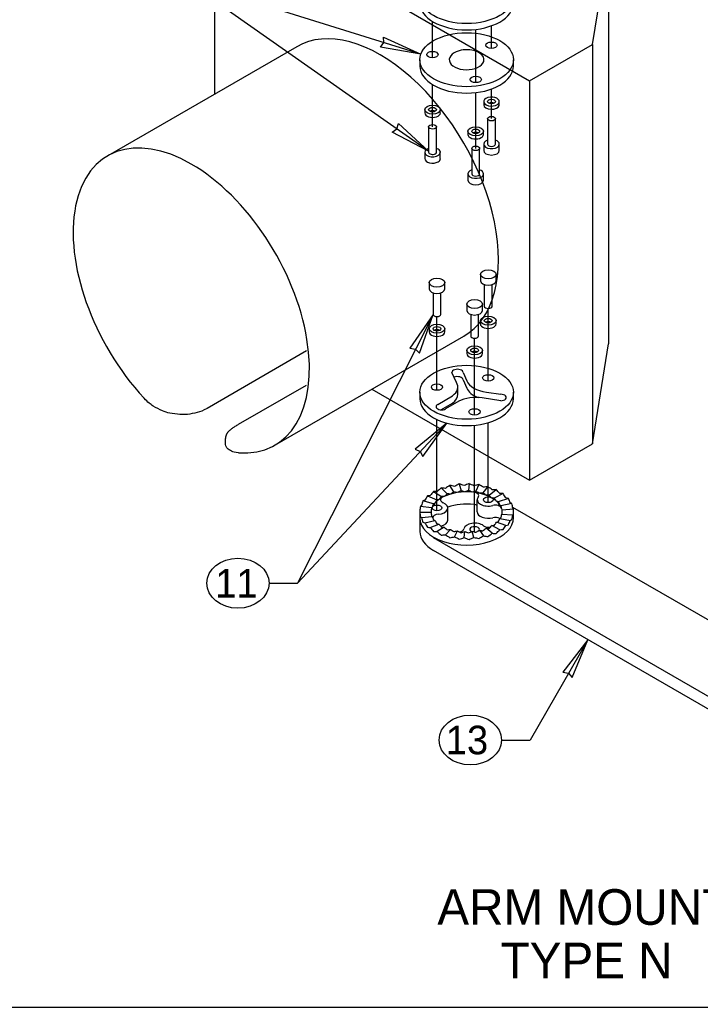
# Model space of a CAD drawing. Extents: x 99862 to 104211, y 98939 to 105076.
# Drawn here: x 100738 to 101120, y 100000 to 100554 of the extents above; entities that cross this region are included whole.
import ezdxf

# ---------------------------------------------------------------- set-up
doc = ezdxf.new("R2010")
doc.units = 0
for name, color, linetype in [('Level 1', 7, 'Continuous'), ('Level 11', 7, 'Continuous'), ('Level 13', 7, 'Continuous'), ('Level 15', 7, 'Continuous'), ('Level 20', 7, 'Continuous'), ('Level 26', 7, 'Continuous')]:
    doc.layers.add(name, color=color, linetype=linetype)

msp = doc.modelspace()

# ---------------------------------------------------------------- linework, layer by layer
at = {"layer": 'Level 1'}
msp.add_lwpolyline([(99862, 99999.5), (103151, 99999.5), (103151, 102075.5), (99862, 102075.5)], close=True, dxfattribs=at)
at = {"layer": 'Level 11'}
for p, q in [((100962.21, 100531.18), (100962.21, 100527.6)), ((101014.71, 100527.6), (101014.71, 100531.18)), ((100998.04, 100507.7), (100998.04, 100505.91)), ((101006.79, 100505.91), (101006.79, 100507.7)), ((100964.95, 100503.14), (100964.95, 100501.35)), ((100973.7, 100501.35), (100973.7, 100503.14)), ((101000.22, 100498.12), (101000.22, 100483.83)), ((101004.6, 100483.83), (101004.6, 100498.12)), ((100967.14, 100493.55), (100967.14, 100479.27)), ((100971.51, 100479.27), (100971.51, 100493.55)), ((100989.2, 100491.02), (100989.2, 100489.24)), ((100997.95, 100489.24), (100997.95, 100491.02)), ((100998.04, 100483.83), (100998.04, 100480.25)), ((101006.79, 100480.25), (101006.79, 100483.83)), ((100964.95, 100479.27), (100964.95, 100475.69)), ((100973.7, 100475.69), (100973.7, 100479.27)), ((100991.39, 100481.44), (100991.39, 100467.15)), ((100995.76, 100467.15), (100995.76, 100481.44)), ((100989.2, 100467.15), (100989.2, 100463.58)), ((100997.95, 100463.58), (100997.95, 100467.15)), ((100996.19, 100410.72), (100996.19, 100407.15)), ((101004.94, 100407.15), (101004.94, 100410.72)), ((100967.42, 100406.16), (100967.42, 100402.59)), ((100976.17, 100402.59), (100976.17, 100406.16)), ((100998.38, 100404.96), (100998.38, 100392.86)), ((101002.75, 100392.86), (101002.75, 100404.96)), ((100969.61, 100400.4), (100969.61, 100388.3)), ((100973.99, 100388.3), (100973.99, 100400.4)), ((100988.54, 100394.05), (100988.54, 100390.47)), ((100997.29, 100390.47), (100997.29, 100394.05)), ((100990.73, 100388.29), (100990.73, 100376.19)), ((100995.1, 100376.19), (100995.1, 100388.29)), ((100996.19, 100384.77), (100996.19, 100382.98)), ((101004.94, 100382.98), (101004.94, 100384.77)), ((100967.42, 100380.21), (100967.42, 100378.42)), ((100976.17, 100378.42), (100976.17, 100380.21)), ((100988.54, 100368.09), (100988.54, 100366.31)), ((100997.29, 100366.31), (100997.29, 100368.09)), ((100982.75, 100350.13), (100980.19, 100355.65)), ((100986.48, 100355.65), (100988.62, 100351.04)), ((100986.48, 100351.54), (100988.62, 100346.93)), ((100983.47, 100343.46), (100983.47, 100347.57)), ((100962.21, 100344.61), (100962.21, 100341.03)), ((100972.23, 100337.81), (100980.59, 100342.63)), ((101007.59, 100339.83), (100997.21, 100341.38)), ((100999.61, 100344.7), (101007.59, 100343.46)), ((101014.71, 100341.03), (101014.71, 100344.61)), ((100974.01, 100334.72), (100980.59, 100338.52)), ((100984.08, 100339.51), (100976.68, 100335.24))]:
    msp.add_line(p, q, dxfattribs=at)
for centre, major_axis in [((100988.46, 100566.64), (26.25, 0)), ((100988.46, 100531.18), (26.25, 0)), ((101002.38, 100539.31), (3.14, 0)), ((100969.3, 100534.06), (3.14, 0)), ((100993.58, 100520.13), (3.14, 0)), ((101002.41, 100507.7), (2.19, 0)), ((100969.33, 100503.14), (-4.38, 0)), ((100969.33, 100503.14), (2.19, 0)), ((101002.41, 100498.12), (2.19, 0)), ((100969.33, 100493.55), (2.19, 0)), ((100993.57, 100491.02), (-4.38, 0)), ((100993.57, 100491.02), (2.19, 0)), ((100993.57, 100481.44), (2.19, 0)), ((101000.56, 100410.72), (4.38, 0)), ((100971.8, 100406.16), (4.38, 0)), ((100992.92, 100394.05), (4.38, 0)), ((101000.56, 100384.77), (-4.38, 0)), ((101000.56, 100384.77), (2.19, 0)), ((100971.8, 100380.21), (-4.38, 0)), ((100971.8, 100380.21), (2.19, 0)), ((100992.92, 100368.09), (-4.38, 0)), ((100992.92, 100368.09), (2.19, 0)), ((100988.46, 100344.61), (26.25, 0)), ((101000.56, 100352.64), (3.14, 0)), ((100971.8, 100347.5), (3.14, 0)), ((100992.92, 100333.56), (3.14, 0))]:
    msp.add_ellipse(centre, major_axis=major_axis, ratio=0.57735, dxfattribs=at)
for centre, major_axis, start_param, end_param in [((100988.46, 100563.07), (26.25, 0), 3.141593, 6.283185), ((100988.46, 100531.18), (9.74, 0), 2.024427, 6.283185), ((100988.46, 100531.18), (9.74, 0), 0, 2.024427), ((100988.46, 100527.6), (26.25, 0), 3.141593, 6.283185), ((101002.41, 100507.7), (-4.38, 0), 4.851782, 8.738551), ((101002.41, 100505.91), (-4.38, 0), 6.283185, 9.281643), ((101002.41, 100505.91), (2.19, 0), 0.785398, 2.356194), ((101002.41, 100507.7), (-4.38, 0), 2.455366, 4.851782), ((101002.41, 100505.91), (-4.38, 0), 2.998458, 3.141593), ((100969.33, 100501.35), (-4.38, 0), 6.283185, 9.424778), ((100969.33, 100501.35), (2.19, 0), 0.785398, 2.356194), ((100993.57, 100489.24), (2.19, 0), 0.785398, 2.356194), ((100993.57, 100489.24), (-4.38, 0), 0, 3.141593), ((101002.41, 100483.83), (4.38, 0), 2.094395, 6.283185), ((101002.41, 100483.83), (2.19, 0), 3.141593, 6.283185), ((101002.41, 100483.83), (4.38, 0), 6.283185, 7.330383), ((100969.33, 100479.27), (4.38, 0), 2.094395, 6.283185), ((100969.33, 100479.27), (2.19, 0), 3.141593, 5.497787), ((100969.33, 100479.27), (2.19, 0), 5.497787, 6.283185), ((100969.33, 100479.27), (4.38, 0), 0, 1.047198), ((101002.41, 100480.25), (4.38, 0), 3.141593, 6.283185), ((100969.33, 100475.69), (4.38, 0), 3.141593, 5.497787), ((100969.33, 100475.69), (4.38, 0), 5.497787, 6.283185), ((100993.57, 100467.15), (4.38, 0), 2.094395, 6.283185), ((100993.57, 100467.15), (2.19, 0), 3.141593, 6.283185), ((100993.57, 100467.15), (4.38, 0), 0, 1.047198), ((100993.57, 100463.58), (4.38, 0), 3.141593, 6.283185), ((101000.56, 100407.15), (4.38, 0), 3.141593, 6.283185), ((100971.8, 100402.59), (4.38, 0), 3.141593, 6.283185), ((100992.92, 100390.47), (4.38, 0), 3.141593, 6.283185), ((101000.56, 100392.86), (2.19, 0), 3.141593, 6.283185), ((100971.8, 100388.3), (2.19, 0), 3.141593, 6.283185), ((101000.56, 100382.98), (2.19, 0), 0.785398, 2.356194), ((100971.8, 100378.42), (2.19, 0), 0.785398, 2.356194), ((101000.56, 100382.98), (-4.38, 0), 6.283185, 9.424778), ((100971.8, 100378.42), (-4.38, 0), 6.283185, 9.424778), ((100992.92, 100376.19), (2.19, 0), 3.141593, 6.283185), ((100992.92, 100366.31), (2.19, 0), 0.785398, 2.356194), ((100992.92, 100366.31), (-4.38, 0), 6.283185, 9.424778), ((100983.34, 100355.65), (3.14, 0), 0, 3.141593), ((100983.34, 100351.54), (3.14, 0), 0, 2.2227), ((101002.46, 100352.69), (14.14, 0), 3.345037, 4.508944), ((100969.33, 100347.57), (14.14, 0), 5.634137, 6.603339), ((101002.46, 100348.58), (14.14, 0), 3.345037, 4.166798), ((100988.46, 100341.03), (26.25, 0), 3.141593, 6.283185), ((100969.33, 100343.46), (14.14, 0), 5.634137, 6.283185), ((100993.59, 100333.56), (14.02, 0), 1.308997, 2.31608), ((101007.59, 100341.65), (3.14, 0), 4.712389, 7.853982), ((100974.46, 100336.52), (3.14, 0), 2.356194, 5.497787)]:
    msp.add_ellipse(centre, major_axis=major_axis, ratio=0.57735, start_param=start_param, end_param=end_param, dxfattribs=at)
at = {"layer": 'Level 13'}
for p, q in [((100974.16, 100290.87), (100977.59, 100287.57)), ((100981.31, 100288.66), (100979.05, 100292.31)), ((100984.35, 100293.13), (100985.34, 100289.29)), ((100989.84, 100293.3), (100989.51, 100289.41)), ((100995.26, 100292.8), (100993.63, 100289.04)), ((101000.38, 100291.66), (100997.52, 100288.17)), ((101001.01, 100286.86), (101004.98, 100289.94)), ((100966.44, 100286.41), (100971.72, 100284.18)), ((100969.89, 100288.88), (100974.35, 100286.06)), ((100994.42, 100277.41), (100994.42, 100284.27)), ((101008.87, 100287.69), (101003.97, 100285.15)), ((101011.86, 100285.04), (101006.24, 100283.14)), ((100968.75, 100279.71), (100962.52, 100280.53)), ((100969.83, 100282.04), (100963.94, 100283.59)), ((100977.91, 100272.79), (100977.91, 100279.65)), ((101013.83, 100282.08), (101007.74, 100280.89)), ((101014.69, 100278.95), (101008.39, 100278.51)), ((101014.28, 100280.15), (101150.39, 100201.57)), ((100962.2, 100277.64), (100962.21, 100274.01)), ((100962.21, 100274.01), (100962.21, 100266.48)), ((100962.24, 100277.36), (100968.53, 100277.31)), ((100963.09, 100274.23), (100969.19, 100274.93)), ((101007.09, 100273.78), (101012.98, 100272.72)), ((101008.17, 100276.11), (101014.4, 100275.78)), ((101014.71, 100274.23), (101014.72, 100277.64)), ((100965.06, 100271.27), (100970.68, 100272.68)), ((100968.05, 100268.61), (100972.95, 100270.66)), ((100975.91, 100268.95), (100971.94, 100266.37)), ((100976.54, 100264.65), (100979.4, 100267.64)), ((101002.76, 100265.44), (100999.33, 100268.25)), ((101007.03, 100267.43), (101002.57, 100269.76)), ((101010.48, 100269.9), (101005.2, 100271.63)), ((101143.14, 100162.89), (100969.9, 100262.91)), ((100981.66, 100263.51), (100983.3, 100266.78)), ((100987.09, 100263.01), (100987.42, 100266.4)), ((100992.57, 100263.18), (100991.58, 100266.53)), ((100995.61, 100267.15), (100997.87, 100264)), ((101143.14, 100155.74), (100969.9, 100255.76))]:
    msp.add_line(p, q, dxfattribs=at)
for centre, major_axis, ratio, start_param, end_param in [((100988.46, 100277.13), (23.98, 15.69), 0.682966, 1.726553, 1.831273), ((100988.46, 100277.13), (-26, 10.17), 0.360362, 5.323611, 5.42833), ((100988.46, 100277.13), (24.51, 15.22), 0.6191, 1.570348, 1.675068), ((100988.46, 100277.13), (-25.82, 11.65), 0.413044, 5.158439, 5.263158), ((100988.46, 100277.13), (24.99, 14.48), 0.557438, 1.415448, 1.520168), ((100988.46, 100277.13), (-25.55, 12.94), 0.468967, 4.997892, 5.102611), ((100988.46, 100277.13), (25.39, 13.51), 0.497899, 1.259485, 1.364205), ((100988.46, 100277.13), (-25.2, 14.02), 0.527399, 4.840753, 4.945473), ((100988.46, 100277.13), (25.69, 12.32), 0.440657, 1.100807, 1.205527), ((100988.46, 100277.13), (-24.76, 14.88), 0.588004, 4.685558, 4.790278), ((100988.46, 100277.13), (25.92, 10.93), 0.386234, 0.938087, 1.042807), ((100988.46, 100277.13), (-24.25, 15.49), 0.650745, 4.530376, 4.635096), ((100988.46, 100277.13), (26.07, 9.36), 0.335596, 0.770561, 0.874936), ((100988.46, 100277.13), (-23.74, 15.68), 0.716006, 4.368664, 4.47373), ((100988.46, 100277.13), (23.05, 15.38), 0.818147, 2.06586, 2.17058), ((100988.46, 100277.13), (-26.2, 6.69), 0.270119, 5.671382, 5.776101), ((100988.46, 100277.13), (23.44, 15.81), 0.749264, 1.888318, 1.993037), ((100988.46, 100277.2), (19.96, 0), 0.57735, 2.313319, 2.894414), ((100988.46, 100277.13), (-26.13, 8.51), 0.312139, 5.494389, 5.599109), ((100988.46, 100277.13), (19.91, -5.08), 0.270119, 2.538903, 2.634509), ((100988.46, 100277.13), (-17.81, -12.01), 0.749264, 5.02991, 5.125516), ((100977.33, 100284.2), (3.5, 0), 0.57735, 2.313319, 4.097386), ((100988.46, 100277.13), (19.85, -6.47), 0.312139, 2.36191, 2.457516), ((100988.46, 100277.2), (19.96, 0), 0.57735, 1.374635, 2.313319), ((100988.46, 100277.13), (-18.22, -11.92), 0.682966, 4.868145, 4.963751), ((100988.46, 100277.13), (19.76, -7.73), 0.360362, 2.191132, 2.286738), ((100988.46, 100277.13), (-18.63, -11.56), 0.6191, 4.711941, 4.807546), ((100988.46, 100277.13), (19.62, -8.85), 0.413044, 2.02596, 2.121566), ((100988.46, 100277.13), (-18.99, -11), 0.557438, 4.557041, 4.652646), ((100988.46, 100277.13), (19.42, -9.83), 0.468967, 1.865413, 1.961019), ((100988.46, 100277.13), (-19.29, -10.26), 0.497899, 4.401077, 4.496683), ((100988.46, 100277.13), (19.15, -10.65), 0.527399, 1.708274, 1.80388), ((100988.46, 100277.13), (-19.52, -9.36), 0.440657, 4.2424, 4.338005), ((100988.46, 100277.2), (19.96, 0), 0.57735, 0.157092, 1.372405), ((100991.74, 100286.51), (3.5, 0), 0.57735, 5.869558, 7.653625), ((100988.46, 100277.13), (18.81, -11.31), 0.588004, 1.55308, 1.648685), ((101000.56, 100284.27), (6.14, 0), 0.57735, 2.727965, 5.138297), ((100988.46, 100277.13), (-19.7, -8.31), 0.386234, 4.07968, 4.175285), ((100988.46, 100277.13), (18.43, -11.77), 0.650745, 1.397898, 1.493503), ((100988.46, 100277.13), (-19.81, -7.11), 0.335596, 3.912154, 4.007414), ((100988.46, 100277.13), (18.04, -11.91), 0.716006, 1.236246, 1.332137), ((100988.46, 100277.13), (-19.88, -5.76), 0.292084, 3.737537, 3.833428), ((100988.46, 100277.13), (17.64, -11.92), 0.783391, 1.072023, 1.167282), ((100988.46, 100277.13), (26.17, 7.58), 0.292084, 0.595944, 0.70101), ((100988.46, 100277.13), (-23.21, 15.69), 0.783391, 4.204501, 4.308875), ((100988.46, 100277.13), (26.22, 5.73), 0.252109, 0.416228, 0.520948), ((100988.46, 100277.13), (-23.03, 14.79), 0.853385, 4.009326, 4.114045), ((100988.46, 100277.13), (25.81, 5.13), 0.947565, 2.798423, 2.903143), ((100988.46, 100277.13), (-26.25, 2.67), 0.213589, 6.04308, 6.1478), ((100988.46, 100277.13), (23.3, 13.64), 0.888613, 2.295514, 2.400234), ((100988.46, 100277.13), (-26.24, 4.73), 0.236491, 5.854579, 5.959298), ((100988.46, 100277.13), (-19.61, -3.9), 0.947565, 5.940016, 6.044735), ((100988.46, 100277.2), (19.96, 0), 0.57735, 2.888908, 3.080118), ((100988.46, 100277.13), (19.95, -2.03), 0.213589, 2.910602, 3.006207), ((100988.46, 100277.13), (-17.7, -10.36), 0.888613, 5.437107, 5.532712), ((100988.46, 100277.13), (19.94, -3.6), 0.236491, 2.7221, 2.817706), ((100988.46, 100277.13), (-17.51, -11.69), 0.818147, 5.207453, 5.303058), ((100971.77, 100279.65), (6.14, 0), 0.57735, 4.828647, 7.238979), ((100988.46, 100270.34), (-19.96, 0), 0.57735, 4.512032, 5.272259), ((100991.74, 100279.65), (-3.5, 0), 0.57735, 3.837098, 4.512032), ((101004.55, 100279.2), (3.5, 0), 0.57735, 0.212638, 1.996705), ((100988.46, 100277.13), (-19.92, -4.35), 0.252109, 3.557821, 3.653426), ((100988.46, 100277.13), (17.5, -11.24), 0.853385, 0.876847, 0.972453), ((100988.46, 100277.13), (-19.95, -2.82), 0.223561, 3.371796, 3.467401), ((100988.46, 100277.13), (18.35, -8.49), 0.922162, 0.569546, 0.665151), ((100988.46, 100277.2), (19.96, 0), 0.57735, 0.147965, 0.166194), ((100988.46, 100277.13), (-19.95, -1.22), 0.206802, 3.181297, 3.276903), ((100988.46, 100277.13), (26.25, 3.71), 0.223561, 0.230203, 0.334923), ((100988.46, 100277.13), (-24.15, 11.18), 0.922162, 3.702024, 3.806744), ((100988.46, 100277.13), (26.26, 1.61), 0.206802, 0.039705, 0.144424), ((100988.46, 100277.13), (25.81, 5.13), 0.947565, 6.044735, 6.149455), ((100988.46, 100277.13), (-26.26, 0.54), 0.203365, 6.234982, 6.339702), ((100988.46, 100274.01), (-26.25, 0), 0.57735, 6.283185, 9.439299), ((100988.46, 100277.13), (-24.15, 11.18), 0.922162, 0.455712, 0.560431), ((100988.46, 100277.13), (26.26, 1.61), 0.206802, 3.286017, 3.390737), ((100988.46, 100277.13), (-23.03, 14.79), 0.853385, 0.763013, 0.867733), ((100988.46, 100277.13), (19.95, -0.41), 0.203365, 3.09339, 3.19811), ((100988.46, 100277.13), (18.35, -8.49), 0.922162, 3.597304, 3.702024), ((100988.46, 100277.13), (-19.95, -1.22), 0.206802, 0.144424, 0.249144), ((100988.46, 100277.13), (17.5, -11.24), 0.853385, 3.904606, 4.009326), ((100972.89, 100274.12), (3.5, 0), 0.57735, 1.687054, 3.090654), ((101000.56, 100277.41), (-6.14, 0), 0.57735, 0, 1.996705), ((101004.55, 100272.34), (-3.5, 0), 0.57735, 3.904893, 5.138297), ((100988.46, 100277.13), (-17.51, -11.69), 0.818147, 2.17058, 2.2753), ((100988.46, 100277.13), (19.95, -2.03), 0.213589, 5.93836, 6.04308), ((100988.46, 100277.13), (-17.7, -10.36), 0.888613, 2.400234, 2.504954), ((100988.46, 100277.13), (19.95, -0.41), 0.203365, 6.130263, 6.32127), ((100988.46, 100277.13), (-19.61, -3.9), 0.947565, 2.921575, 3.007863), ((100988.46, 100277.13), (-26.25, 2.67), 0.213589, 2.796768, 2.901488), ((100988.46, 100277.13), (23.3, 13.64), 0.888613, 5.541827, 5.646547), ((100988.46, 100277.13), (-26.26, 0.54), 0.203365, 2.98867, 3.09339), ((100988.46, 100277.13), (26.25, 3.71), 0.223561, 3.476515, 3.581235), ((100988.46, 100277.13), (-23.21, 15.69), 0.783391, 0.958188, 1.062908), ((100988.46, 100277.13), (26.22, 5.73), 0.252109, 3.662541, 3.766915), ((100988.46, 100277.13), (-23.74, 15.68), 0.716006, 1.122007, 1.227072), ((100988.46, 100277.13), (-19.95, -2.82), 0.223561, 0.334923, 0.439643), ((100988.46, 100277.13), (17.64, -11.92), 0.783391, 4.099781, 4.204501), ((100988.46, 100277.13), (-19.92, -4.35), 0.252109, 0.520948, 0.625322), ((100988.46, 100277.13), (18.04, -11.91), 0.716006, 4.263599, 4.368664), ((100971.77, 100272.79), (6.14, 0), 0.57735, 5.069342, 6.283185), ((100988.46, 100277.13), (-19.88, -5.76), 0.292084, 0.70101, 0.806075), ((100988.46, 100277.13), (18.43, -11.77), 0.650745, 4.426002, 4.530376), ((100988.46, 100277.13), (-19.81, -7.11), 0.335596, 0.874936, 0.979655), ((100988.46, 100277.13), (18.81, -11.31), 0.588004, 4.580838, 4.685558), ((100983.42, 100268.15), (3.5, 0), 0.57735, 4.992525, 6.185337), ((100993.02, 100267.61), (6.14, 0), 0.57735, 0.633413, 3.043745), ((100992.92, 100267.59), (2.73, 0), 0.57735, 5.958058, 10.322476), ((100988.46, 100277.13), (-18.63, -11.56), 0.6191, 1.675068, 1.779788), ((101000.79, 100270.9), (3.5, 0), 0.57735, 3.775005, 5.014613), ((100988.46, 100277.13), (19.85, -6.47), 0.312139, 5.389669, 5.494389), ((100988.46, 100277.13), (-18.22, -11.92), 0.682966, 1.831273, 1.935992), ((100988.46, 100277.13), (19.91, -5.08), 0.270119, 5.566662, 5.671382), ((100988.46, 100277.13), (-17.81, -12.01), 0.749264, 1.993037, 2.097757), ((100988.46, 100277.13), (19.94, -3.6), 0.236491, 5.749859, 5.854579), ((100988.46, 100277.13), (23.44, 15.81), 0.749264, 5.13463, 5.23935), ((100988.46, 100277.13), (-26.24, 4.73), 0.236491, 2.608266, 2.712986), ((100988.46, 100277.13), (23.05, 15.38), 0.818147, 5.312172, 5.416892), ((100988.46, 100266.48), (26.25, 0), 0.57735, 3.141593, 3.926991), ((100988.46, 100277.13), (26.17, 7.58), 0.292084, 3.842602, 3.947667), ((100988.46, 100277.13), (-24.25, 15.49), 0.650745, 1.284409, 1.388784), ((100988.46, 100277.13), (26.07, 9.36), 0.335596, 4.016528, 4.121248), ((100988.46, 100277.13), (-24.76, 14.88), 0.588004, 1.439246, 1.543965), ((100988.46, 100277.13), (25.92, 10.93), 0.386234, 4.184399, 4.289119), ((100988.46, 100277.13), (-19.7, -8.31), 0.386234, 1.042807, 1.147526), ((100988.46, 100277.13), (-25.2, 14.02), 0.527399, 1.59444, 1.69916), ((100988.46, 100277.13), (19.15, -10.65), 0.527399, 4.736033, 4.840753), ((100988.46, 100277.13), (25.69, 12.32), 0.440657, 4.34712, 4.45184), ((100988.46, 100277.13), (-19.52, -9.36), 0.440657, 1.205527, 1.310247), ((100988.46, 100277.13), (-25.55, 12.94), 0.468967, 1.751579, 1.856299), ((100988.46, 100277.13), (19.42, -9.83), 0.468967, 4.893172, 4.997892), ((100988.46, 100277.13), (-19.29, -10.26), 0.497899, 1.364205, 1.468924), ((100988.46, 100277.13), (25.39, 13.51), 0.497899, 4.505797, 4.610517), ((100988.46, 100277.13), (19.62, -8.85), 0.413044, 5.053719, 5.158439), ((100988.46, 100277.13), (-25.82, 11.65), 0.413044, 1.912126, 2.016846), ((100988.46, 100277.13), (-18.99, -11), 0.557438, 1.520168, 1.624888), ((100988.46, 100277.13), (24.99, 14.48), 0.557438, 4.66176, 4.76648), ((100988.46, 100277.13), (19.76, -7.73), 0.360362, 5.218891, 5.323611), ((100988.46, 100277.13), (-26, 10.17), 0.360362, 2.077298, 2.182018), ((100988.46, 100277.13), (24.51, 15.22), 0.6191, 4.81666, 4.92138), ((100988.46, 100277.13), (-26.13, 8.51), 0.312139, 2.248076, 2.352796), ((100988.46, 100277.13), (23.98, 15.69), 0.682966, 4.972865, 5.077585), ((100988.46, 100277.13), (-26.2, 6.69), 0.270119, 2.425069, 2.529789)]:
    msp.add_ellipse(centre, major_axis=major_axis, ratio=ratio, start_param=start_param, end_param=end_param, dxfattribs=at)
for centre in [(101000.56, 100284.27), (100971.8, 100279.71)]:
    msp.add_ellipse(centre, major_axis=(2.73, 0), ratio=0.57735, dxfattribs=at)
at = {"layer": 'Level 15'}
for p, q in [((100967.14, 100479.81), (100831.11, 100575.45)), ((100962.76, 100534.27), (100831.11, 100575.45)), ((100969.3, 100532.25), (100969.3, 100552.71)), ((100993.58, 100518.31), (100993.58, 100548.2)), ((101002.38, 100537.49), (101002.38, 100550.22)), ((100969.3, 100493.55), (100969.3, 100517.24)), ((100993.58, 100481.44), (100993.58, 100512.74)), ((101002.38, 100498.12), (101002.38, 100514.75)), ((101000.56, 100350.83), (101000.56, 100391.6)), ((100969.61, 100388.3), (100893.62, 100237.42)), ((100971.8, 100345.68), (100971.8, 100387.04)), ((100992.92, 100331.75), (100992.92, 100374.92)), ((100971.8, 100278.13), (100971.8, 100329.32)), ((100977.26, 100327.33), (100893.62, 100237.42)), ((100992.92, 100266.17), (100992.92, 100326.1)), ((101000.56, 100282.69), (101000.56, 100327.59)), ((100877.62, 100237.42), (100893.62, 100237.42)), ((101056.52, 100205.75), (101024.02, 100149.46)), ((101008.02, 100149.46), (101024.02, 100149.46))]:
    msp.add_line(p, q, dxfattribs=at)
for points in [[(100962.76, 100534.27), (100940.09, 100538.24), (100941.98, 100540.77), (100941.87, 100543.93)], [(100967.14, 100479.81), (100946.75, 100490.5), (100949.33, 100492.33), (100950.18, 100495.38)], [(100969.61, 100388.3), (100956.68, 100369.26), (100959.82, 100368.86), (100962.01, 100366.57)], [(100977.26, 100327.33), (100959.53, 100312.65), (100962.43, 100311.39), (100963.9, 100308.58)], [(101056.52, 100205.75), (101042.52, 100187.47), (101045.63, 100186.9), (101047.69, 100184.49)]]:
    msp.add_lwpolyline(points, close=True, dxfattribs=at)
at = {"layer": 'Level 20'}
for centre in [(100860.12, 100237.42), (100990.52, 100149.46)]:
    msp.add_ellipse(centre, major_axis=(-17.5, 0), ratio=0.8, dxfattribs=at)
at = {"layer": 'Level 26'}
for p, q in [((100847.04, 100621.43), (101023.82, 100519.36)), ((100847.04, 100621.43), (100847.04, 100512.28)), ((101059.17, 100539.78), (101068.01, 100595.91)), ((101068.01, 100595.91), (101068.01, 100371.79)), ((101023.82, 100519.36), (101059.17, 100539.78)), ((101059.17, 100539.78), (101059.17, 100315.65)), ((100893.17, 100538.51), (100787.11, 100477.27)), ((101023.82, 100519.36), (101023.82, 100295.24)), ((100880.86, 100314.89), (100986.92, 100376.13)), ((100898.69, 100367.79), (100842.82, 100335.53)), ((101059.17, 100315.65), (101068.01, 100371.79)), ((100860.5, 100326.61), (100898.57, 100348.59)), ((100935.31, 100346.34), (101023.82, 100295.24)), ((100853.18, 100316.17), (100853.18, 100317.48)), ((101023.82, 100295.24), (101059.17, 100315.65))]:
    msp.add_line(p, q, dxfattribs=at)
for centre, start_param, end_param in [((100940.05, 100457.32), 0, 3.141593), ((100833.98, 100396.08), 5.909304, 11.369456)]:
    msp.add_ellipse(centre, major_axis=(46.88, -81.19), ratio=0.57735, start_param=start_param, end_param=end_param, dxfattribs=at)
for points, degree in [([(100842.82, 100335.53), (100840.43, 100334.15), (100837.6, 100333.14), (100831.4, 100332.03), (100828.04, 100331.95), (100821.46, 100332.86), (100818.18, 100333.86), (100812.3, 100336.86), (100809.65, 100338.87), (100807.47, 100341.24)], 3), ([(100853.18, 100317.46), (100853.18, 100320.37), (100855.81, 100323.91), (100860.5, 100326.61)], 2), ([(100860.5, 100310.62), (100858.31, 100310.78), (100856.51, 100311.34), (100853.95, 100313.21), (100853.23, 100314.5), (100853.18, 100316.02), (100853.18, 100316.07), (100853.18, 100316.12)], 3)]:
    msp.add_open_spline(points, degree=degree, dxfattribs=at)

# ---------------------------------------------------------------- texts
at = {"layer": 'Level 20'}
for s, height, p in [('11', 16, (100847.4, 100229.42)), ('13', 16, (100976.74, 100141.46)), ('ARM MOUNT', 20, (100972.01, 100045.75)), ('TYPE N', 20, (101007.46, 100015.75))]:
    msp.add_text(s, height=height, dxfattribs=at).set_placement(p)

doc.saveas('drawing.dxf')
